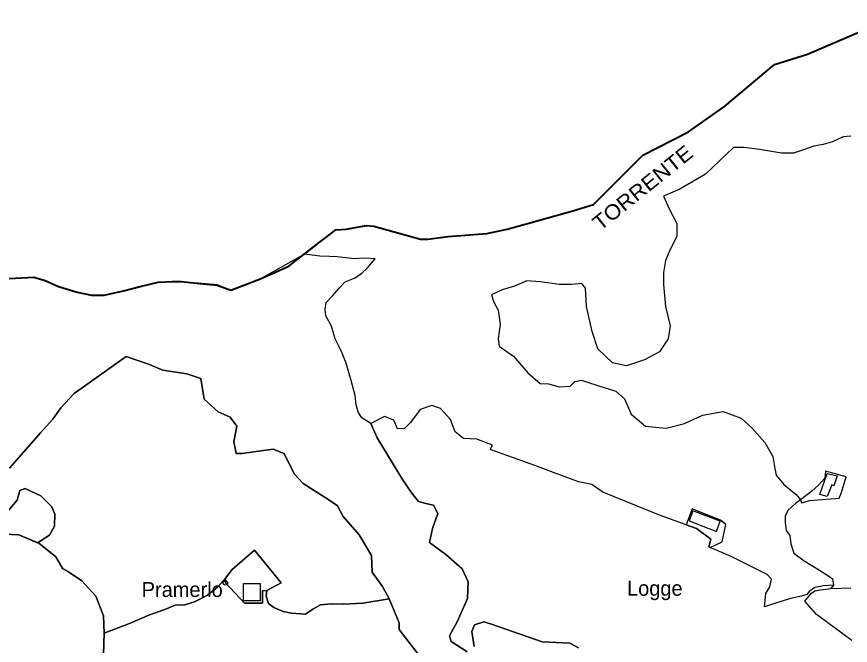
# Model space of a CAD drawing. Extents: x 645880 to 658994, y 884400 to 894744.
# Drawn here: x 652953 to 653901, y 892365 to 893080 of the extents above; entities that cross this region are included whole.
import ezdxf
from ezdxf.enums import TextEntityAlignment as Align

# ---------------------------------------------------------------- set-up
doc = ezdxf.new("R2010")
doc.units = 0
doc.header["$LTSCALE"] = 10
doc.header["$PDMODE"] = 32
doc.header["$PDSIZE"] = 5
for name, color, linetype, lineweight in [('16', 7, 'Continuous', 25), ('18', 7, 'Continuous', 25), ('2', 7, 'Continuous', 25), ('3', 7, 'Continuous', 25), ('4', 7, 'Continuous', 25), ('55', 7, 'Continuous', 25), ('59', 7, 'Continuous', 40)]:
    doc.layers.add(name, color=color, linetype=linetype, lineweight=lineweight)
doc.layers.add('60', color=7, linetype='Continuous')

msp = doc.modelspace()

# ---------------------------------------------------------------- linework, layer by layer
at = {"layer": '16'}
for p, q in [((653190.29, 892436.39), (653190.29, 892441.93)), ((653882.19, 892433.95), (653879.56, 892429.9)), ((653051.59, 892398.95), (653052.56, 892379.04))]:
    msp.add_line(p, q, dxfattribs=at)
for points in [[(653901.94, 892944.55), (653893.18, 892943.55), (653880.8, 892938.05), (653870.49, 892935.05), (653859.66, 892933.05), (653847.8, 892929.05), (653836.46, 892925.04), (653823.06, 892925.04)], [(653823.06, 892925.04), (653795.73, 892929.55), (653780.32, 892931.47), (653768.46, 892931.47), (653736.49, 892901.21)], [(653736.49, 892901.21), (653707.44, 892884.17), (653688.64, 892876.42), (653695.12, 892861.75), (653703.76, 892844.99), (653703.76, 892830.32), (653696.2, 892815.66), (653690.8, 892803.09), (653688.64, 892789.47), (653688.64, 892775.85), (653690.8, 892750.71), (653696.2, 892728.71), (653694.04, 892714.04), (653684.32, 892699.38), (653667.04, 892689.95), (653646.67, 892683.41), (653630.59, 892686.58), (653614.13, 892702.52), (653607.65, 892722.42), (653601.17, 892750.71), (653600.09, 892771.66), (653595.77, 892776.9), (653583.89, 892775.85), (653569.85, 892775.85), (653548.25, 892778.99), (653533.14, 892780.04), (653519.1, 892773.76), (653505.06, 892769.57), (653493.17, 892764.11), (653495.85, 892755.82), (653500.74, 892746.52), (653502.9, 892730.8), (653500.74, 892714.04), (653501.82, 892705.66), (653518.26, 892694.38), (653534.22, 892675.28), (653548.24, 892663.17), (653557.97, 892662.71), (653569.92, 892659.27), (653582.59, 892660.25)], [(653203.52, 892614.56), (653195.7, 892625.02), (653182.11, 892631), (653166.08, 892645.41), (653162.34, 892668.8), (653146.57, 892674.06), (653119.08, 892678.31), (653103.06, 892685.11), (653077.52, 892693.81), (653018.29, 892651.67), (653003.07, 892635.36), (652994.14, 892622.77), (652979.98, 892607.09), (652969.17, 892594.47), (652944.85, 892566.84)], [(653582.59, 892660.25), (653587.71, 892665.61), (653595.26, 892667.08), (653602.25, 892664.81), (653615.21, 892660.62), (653634.64, 892654.33), (653644.47, 892645.62), (653651.92, 892628.14), (653668.12, 892614.52), (653691.88, 892612.43), (653712.4, 892617.67), (653732.91, 892627.09), (653756.67, 892631.28), (653777, 892623.93), (653789.42, 892612.41), (653803.89, 892595.98), (653813.07, 892580.26), (653815.23, 892566.64), (653816.85, 892558.79), (653825.49, 892548.31), (653839.53, 892536.79)], [(653860.67, 892427.28), (653867.15, 892428.33), (653879.56, 892429.9), (653882.19, 892433.95), (653870.58, 892433), (653860.87, 892431.29), (653854.21, 892426.72), (653851.73, 892423.1), (653845.64, 892421.38), (653834.79, 892419.1), (653815.95, 892413.19), (653803.63, 892409.25), (653804.98, 892424.44), (653809.84, 892432.03), (653811.45, 892440.67), (653806.81, 892445.76), (653794.45, 892451.94), (653765.83, 892466.6), (653741.96, 892476.66), (653741.93, 892476.63), (653740.33, 892477.49), (653742.58, 892486.28), (653726.15, 892498.12), (653714.32, 892502.38), (653714.33, 892502.42), (653684.13, 892513.29), (653619.72, 892539.61), (653607.24, 892548.16), (653592.12, 892551.45), (653542.18, 892569.87), (653491.58, 892588.3), (653494.08, 892592.98), (653476.38, 892599.83), (653461.15, 892600.6), (653451.82, 892608.21), (653446.38, 892622.39), (653435.21, 892634.89), (653425.35, 892638.18), (653412.04, 892633.55), (653400.82, 892618.89)], [(653400.82, 892618.89), (653394.16, 892611.84), (653385.98, 892611.46), (653381.98, 892621.36), (653371.32, 892625.74), (653355.69, 892617.78), (653362.92, 892601.33), (653391.75, 892554.1), (653402.26, 892538.31), (653410.15, 892529.1), (653418.48, 892526.67), (653426.95, 892524.88), (653432.08, 892515.29), (653425.92, 892498.17), (653422.64, 892482.38), (653441.04, 892468.56), (653459.51, 892452.39), (653466.42, 892437.45), (653465.75, 892418.71), (653454.18, 892392.24), (653445.24, 892376.33), (653447.25, 892369.86), (653465.3, 892357.81)], [(653237.32, 892427.62), (653236.83, 892421.18), (653239.55, 892413), (653245.55, 892408.36), (653255.9, 892403.72), (653265.72, 892401.81), (653281.52, 892401), (653289.7, 892406.45), (653298.42, 892411.63), (653310.68, 892412.45), (653325.13, 892412.18), (653346.66, 892413.27), (653376.76, 892418.1), (653369, 892432.32), (653357.41, 892448.61), (653356.74, 892467.57), (653342.63, 892490.91), (653324.27, 892511.86), (653317.94, 892523.99), (653308.07, 892530.72), (653278.91, 892549.58), (653268.67, 892560.34), (653257.03, 892583.64), (653244.71, 892588.57), (653209.13, 892583.64), (653202.65, 892583.64), (653200.08, 892596.72), (653203.52, 892614.56)], [(652941.13, 892515.74), (652953.4, 892530.65), (652956.35, 892541.57), (652962.59, 892543.74), (652980.25, 892535.58), (652993.02, 892522.81)], [(653839.53, 892536.79), (653844.39, 892531.03), (653838.99, 892526.84), (653830.35, 892518.98), (653827.11, 892512.69), (653827.11, 892504.84), (653828.19, 892495.93), (653832.51, 892490.17), (653833.59, 892480.74), (653836.83, 892470.27), (653848.71, 892461.36), (653865.99, 892450.89), (653876.79, 892444.08), (653881.11, 892440.93), (653882.19, 892433.95), (653879.56, 892429.9), (653901.7, 892430.95)], [(652993.02, 892522.81), (652996.28, 892514.38), (652996.11, 892501.04), (652990.2, 892490.51), (652976.8, 892482.12)], [(652976.8, 892482.12), (652978.22, 892481.53), (652997.67, 892466.1), (653005.6, 892452.45), (653005.72, 892452.31), (653011.76, 892448.91), (653027.23, 892438.87), (653042.85, 892421.21), (653051.59, 892398.95)], [(653052.56, 892379.04), (653081.38, 892390.35), (653103.24, 892399.51), (653121.56, 892406.02), (653133.08, 892411.04), (653144.31, 892411.63), (653155.24, 892414.88), (653170.02, 892422.28), (653181.84, 892432.03), (653190.29, 892441.93), (653198.12, 892451.62), (653223.49, 892473.77), (653253.92, 892436.39), (653237.32, 892427.62)], [(653190.29, 892441.93), (653181.84, 892432.03), (653170.02, 892422.28), (653155.24, 892414.88), (653144.31, 892411.63)], [(653376.76, 892418.1), (653346.66, 892413.27), (653325.13, 892412.18), (653310.68, 892412.45), (653298.42, 892411.63), (653289.7, 892406.45), (653281.52, 892401), (653265.72, 892401.81), (653255.9, 892403.72), (653245.55, 892408.36), (653239.55, 892413), (653236.83, 892421.18), (653237.32, 892427.62), (653232.62, 892427.4), (653232.71, 892413.31), (653211.96, 892413.31), (653190.29, 892436.39)], [(653902.88, 892370.97), (653862.92, 892400.3), (653849.64, 892415.48), (653856.89, 892424.66), (653860.67, 892427.28)], [(653414.88, 892348.35), (653387.94, 892383.22), (653387.94, 892391.12), (653376.76, 892418.1)], [(653144.31, 892411.63), (653133.08, 892411.04), (653121.56, 892406.02), (653103.24, 892399.51)], [(653103.24, 892399.51), (653081.38, 892390.35), (653052.56, 892379.04)], [(653473.24, 892363.94), (653470.61, 892381.05), (653473.78, 892388.82), (653484.41, 892392.24), (653492.95, 892389.6), (653550.78, 892369.21), (653582.27, 892367.91), (653592.12, 892362.65)], [(653052.56, 892379.04), (653052.03, 892367.52), (653051.51, 892341.5), (653053.91, 892333.42), (653058.55, 892320.5), (653061.07, 892316.84), (653070.81, 892305.95), (653093, 892285.93), (653111.55, 892271.51), (653120.29, 892265.68), (653125.07, 892263.52), (653128.58, 892262.48), (653136.89, 892259.79), (653138.07, 892259.44), (653150.65, 892258.57), (653173.25, 892258.73), (653193.46, 892272.72), (653209.64, 892279.81), (653231.4, 892284.64), (653255.59, 892279.26)]]:
    msp.add_lwpolyline(points, dxfattribs=at)
msp.add_point((653190.29, 892436.39), dxfattribs=at)
at = {"layer": '18'}
for points in [[(653665.35, 892922.98), (653717.24, 892949.39), (653737.66, 892963.83), (653758.08, 892978.27), (653786.58, 893002.21), (653815.08, 893026.14), (653833.79, 893031.92), (653852.51, 893037.7), (653873.78, 893046.77), (653895.05, 893055.85), (653923.38, 893068.13)], [(653901.94, 892944.55), (653893.18, 892943.55), (653880.8, 892938.05), (653870.49, 892935.05), (653859.66, 892933.05), (653847.8, 892929.05), (653836.46, 892925.04), (653823.06, 892925.04), (653795.73, 892929.55), (653780.32, 892931.47), (653768.46, 892931.47), (653736.49, 892901.21)], [(653538.06, 892846.19), (653585.7, 892859.4), (653609.2, 892866.86), (653637.27, 892894.92), (653665.35, 892922.98)], [(653736.49, 892901.21), (653707.44, 892884.17), (653688.64, 892876.42), (653695.12, 892861.75), (653703.76, 892844.99), (653703.76, 892830.32), (653696.2, 892815.66), (653690.8, 892803.09), (653688.64, 892789.47), (653688.64, 892775.85), (653690.8, 892750.71), (653696.2, 892728.71), (653694.04, 892714.04), (653684.32, 892699.38), (653667.04, 892689.95), (653646.67, 892683.41), (653630.59, 892686.58), (653614.13, 892702.52), (653607.65, 892722.42), (653601.17, 892750.71), (653600.09, 892771.66), (653595.77, 892776.9), (653583.89, 892775.85), (653569.85, 892775.85), (653548.25, 892778.99), (653533.14, 892780.04), (653519.1, 892773.76), (653505.06, 892769.57), (653493.17, 892764.11), (653495.85, 892755.82), (653500.74, 892746.52), (653502.9, 892730.8), (653500.74, 892714.04), (653501.82, 892705.66), (653518.26, 892694.38), (653534.22, 892675.28), (653548.24, 892663.17), (653557.97, 892662.71), (653569.92, 892659.27), (653582.59, 892660.25)], [(653327.92, 892838.76), (653339.41, 892840.83), (653350.89, 892842.89), (653359.4, 892842.07), (653412.14, 892827.21), (653420.65, 892827.21), (653432.13, 892828.86), (653443.62, 892830.51), (653465.74, 892832.16), (653487.86, 892833.81), (653510.83, 892838.76), (653524.45, 892842.47), (653538.06, 892846.19)], [(653355.69, 892617.78), (653345.71, 892623.97), (653341.26, 892630.4), (653339.28, 892638.82), (653337.8, 892649.7), (653333.35, 892666.53), (653327.91, 892686.33), (653322.47, 892699.69), (653315.05, 892714.05), (653311.09, 892728.4), (653304.66, 892740.28), (653303.67, 892747.71), (653305.15, 892755.13), (653312.08, 892763.05), (653319.99, 892771.96), (653326.42, 892778.89), (653337.8, 892783.34), (653345.71, 892788.79), (653352.14, 892794.73), (653360.86, 892804.96), (653348.19, 892805.62), (653337.31, 892805.12), (653317.52, 892807.1), (653308.62, 892807.6), (653297.74, 892808.09), (653280.52, 892810.27), (653302.39, 892827.63), (653316.01, 892837.94), (653327.92, 892838.76)], [(653355.69, 892617.78), (653345.71, 892623.97), (653341.26, 892630.4), (653339.28, 892638.82), (653337.8, 892649.7), (653333.35, 892666.53), (653327.91, 892686.33), (653322.47, 892699.69), (653315.05, 892714.05), (653311.09, 892728.4), (653304.66, 892740.28), (653303.67, 892747.71), (653305.15, 892755.13), (653312.08, 892763.05), (653319.99, 892771.96), (653326.42, 892778.89), (653337.8, 892783.34), (653345.71, 892788.79), (653352.14, 892794.73), (653360.86, 892804.96), (653348.19, 892805.62), (653337.31, 892805.12), (653317.52, 892807.1), (653308.62, 892807.6), (653297.74, 892808.09), (653280.52, 892810.27), (653230.93, 892782.64), (653196.39, 892769.43), (653181.06, 892775.21), (653150.83, 892778.1), (653140.19, 892779.34), (653129.97, 892779.34), (653113.79, 892778.51), (653093.35, 892773.56), (653074.61, 892768.6), (653052.47, 892763.64), (653037.99, 892763.64), (653021.81, 892766.95), (653011.17, 892770.25), (653000.52, 892773.56)], [(653000.52, 892773.56), (652985.19, 892780.17), (652972.42, 892784.3), (652944.32, 892782.64)], [(652944.85, 892566.84), (652969.17, 892594.47), (652979.98, 892607.09), (652994.14, 892622.77), (653003.07, 892635.36), (653018.29, 892651.67), (653077.52, 892693.81), (653103.06, 892685.11), (653119.08, 892678.31), (653146.57, 892674.06), (653162.34, 892668.8), (653166.08, 892645.41), (653182.11, 892631)], [(653582.59, 892660.25), (653587.71, 892665.61), (653595.26, 892667.08), (653602.25, 892664.81), (653615.21, 892660.62), (653634.64, 892654.33), (653644.47, 892645.62), (653651.92, 892628.14), (653668.12, 892614.52), (653691.88, 892612.43), (653712.4, 892617.67), (653732.91, 892627.09), (653756.67, 892631.28), (653777, 892623.93), (653789.42, 892612.41), (653803.89, 892595.98), (653813.07, 892580.26), (653815.23, 892566.64), (653816.85, 892558.79), (653825.49, 892548.31), (653839.53, 892536.79), (653844.39, 892531.03), (653838.99, 892526.84), (653830.35, 892518.98), (653827.11, 892512.69), (653827.11, 892504.84), (653828.19, 892495.93), (653832.51, 892490.17), (653833.59, 892480.74), (653836.83, 892470.27), (653848.71, 892461.36), (653865.99, 892450.89), (653876.79, 892444.08), (653881.11, 892440.93), (653882.19, 892433.95), (653870.58, 892433), (653860.87, 892431.29), (653854.21, 892426.72), (653851.73, 892423.1), (653845.64, 892421.38)], [(653845.64, 892421.38), (653834.79, 892419.1), (653815.95, 892413.19), (653803.63, 892409.25), (653804.98, 892424.44), (653809.84, 892432.03), (653811.45, 892440.67), (653806.81, 892445.76), (653794.45, 892451.94), (653765.83, 892466.6), (653741.96, 892476.66), (653755.33, 892483.12), (653759.48, 892502.96), (653753.49, 892507.57), (653721.21, 892520.49), (653714.33, 892502.42), (653684.13, 892513.29), (653619.72, 892539.61), (653607.24, 892548.16), (653592.12, 892551.45), (653542.18, 892569.87), (653491.58, 892588.3), (653494.08, 892592.98), (653476.38, 892599.83), (653461.15, 892600.6), (653451.82, 892608.21), (653446.38, 892622.39), (653435.21, 892634.89), (653425.35, 892638.18), (653412.04, 892633.55), (653400.82, 892618.89), (653394.16, 892611.84), (653385.98, 892611.46), (653381.98, 892621.36), (653371.32, 892625.74), (653355.69, 892617.78)], [(653182.11, 892631), (653195.7, 892625.02), (653203.52, 892614.56), (653200.08, 892596.72), (653202.65, 892583.64), (653209.13, 892583.64), (653244.71, 892588.57), (653257.03, 892583.64), (653268.67, 892560.34), (653278.91, 892549.58), (653308.07, 892530.72), (653317.94, 892523.99), (653324.27, 892511.86), (653342.63, 892490.91), (653356.74, 892467.57), (653357.41, 892448.61), (653369, 892432.32), (653376.76, 892418.1), (653387.94, 892391.12), (653387.94, 892383.22), (653414.88, 892348.35)], [(653465.3, 892357.81), (653447.25, 892369.86), (653445.24, 892376.33), (653454.18, 892392.24), (653465.75, 892418.71), (653466.42, 892437.45), (653459.51, 892452.39), (653441.04, 892468.56), (653422.64, 892482.38), (653425.92, 892498.17), (653432.08, 892515.29), (653426.95, 892524.88), (653418.48, 892526.67), (653410.15, 892529.1), (653402.26, 892538.31), (653391.75, 892554.1), (653362.92, 892601.33), (653355.69, 892617.78)], [(652996.11, 892501.04), (652996.28, 892514.38), (652993.02, 892522.81), (652980.25, 892535.58), (652962.59, 892543.74), (652956.35, 892541.57), (652953.4, 892530.65), (652941.13, 892515.74)], [(652827.89, 892453.5), (652831.54, 892463.14), (652859.71, 892483.55), (652885.54, 892487.96), (652902.63, 892487.4), (652912.11, 892487.8), (652930.58, 892492.23), (652955.56, 892490.98), (652976.8, 892482.12), (652990.2, 892490.51), (652996.11, 892501.04)], [(653902.88, 892370.97), (653862.92, 892400.3), (653849.64, 892415.48), (653856.89, 892424.66), (653860.67, 892427.28), (653867.15, 892428.33), (653879.56, 892429.9), (653901.7, 892430.95)], [(653592.12, 892362.65), (653582.27, 892367.91), (653550.78, 892369.21), (653492.95, 892389.6), (653484.41, 892392.24), (653473.78, 892388.82), (653470.61, 892381.05), (653473.24, 892363.94)]]:
    msp.add_lwpolyline(points, dxfattribs=at)
at = {"layer": '2'}
for points in [[(653886.32, 892558.03), (653882.54, 892546.7), (653880.1, 892547.81), (653874.77, 892534.71), (653866.56, 892536.93), (653875, 892560.92)], [(653722.05, 892518.33), (653717.83, 892506.9), (653748.93, 892494.77), (653753.14, 892506.73)]]:
    msp.add_lwpolyline(points, close=True, dxfattribs=at)
at = {"layer": '3'}
for points in [[(653223.49, 892473.77), (653198.12, 892451.62), (653190.29, 892441.93), (653190.29, 892436.39)], [(653190.29, 892436.39), (653211.96, 892413.31), (653232.71, 892413.31), (653232.62, 892427.4), (653237.32, 892427.62), (653253.92, 892436.39), (653223.49, 892473.77)]]:
    msp.add_lwpolyline(points, dxfattribs=at)
msp.add_lwpolyline([(653210.93, 892435.63), (653229.97, 892435.72), (653229.97, 892416.06), (653211.02, 892415.97)], close=True, dxfattribs=at)
msp.add_point((653190.29, 892436.39), dxfattribs=at)
at = {"layer": '4'}
for points in [[(653844.39, 892531.03), (653845.79, 892527.54), (653855.25, 892530.16), (653863.78, 892531.01), (653888.68, 892532.85), (653890.99, 892539.31), (653896.62, 892556.95), (653873.05, 892563.57), (653872.08, 892555.46), (653865.17, 892547.62), (653857.33, 892540.7)], [(653753.46, 892507.54), (653721.18, 892520.46), (653714.3, 892502.39), (653726.15, 892498.12), (653742.58, 892486.28), (653740.33, 892477.49), (653741.93, 892476.63), (653755.3, 892483.09), (653759.45, 892502.93)]]:
    msp.add_lwpolyline(points, close=True, dxfattribs=at)
at = {"layer": '55'}
msp.add_lwpolyline([(653051.51, 892341.5), (653052.03, 892367.52), (653052.56, 892379.04), (653051.59, 892398.95), (653042.85, 892421.21), (653027.23, 892438.87), (653011.76, 892448.91), (653005.72, 892452.31), (653005.6, 892452.45), (652997.67, 892466.1), (652978.22, 892481.53), (652955.56, 892490.98), (652930.58, 892492.23)], dxfattribs=at)
at = {"layer": '59'}
for points in [[(653196.36, 892769.4), (653230.9, 892782.61), (653262.38, 892796.64), (653288.75, 892817.28), (653315.98, 892837.91), (653327.89, 892838.73), (653350.86, 892842.86), (653359.37, 892842.04), (653412.11, 892827.18), (653420.62, 892827.18), (653443.59, 892830.48), (653487.83, 892833.78), (653510.8, 892838.73), (653538.03, 892846.16), (653585.67, 892859.37), (653609.17, 892866.83), (653665.32, 892922.95), (653717.21, 892949.36), (653758.05, 892978.24), (653815.05, 893026.11), (653852.48, 893037.67), (653895.02, 893055.82), (653951.68, 893080.38)], [(652944.29, 892782.61), (652972.39, 892784.27), (652985.16, 892780.14), (653000.49, 892773.53), (653021.78, 892766.92), (653037.96, 892763.61), (653052.44, 892763.61), (653074.58, 892768.57), (653093.32, 892773.53), (653113.76, 892778.48), (653129.94, 892779.31), (653140.16, 892779.31), (653161.45, 892776.83), (653181.03, 892775.18), (653196.36, 892769.4)]]:
    msp.add_lwpolyline(points, dxfattribs=at)

# ---------------------------------------------------------------- texts
at = {"layer": '60', "width": 1.1}
msp.add_text('TORRENTE', height=17, rotation=38.81, dxfattribs=at).set_placement((653670.28, 892879.2), align=Align.CENTER)
at = {"layer": '60'}
for s, p in [('Pramerlo', (653141.22, 892420.37)), ('Logge', (653678.83, 892421.76))]:
    msp.add_text(s, height=17, dxfattribs=at).set_placement(p, align=Align.CENTER)

doc.saveas('drawing.dxf')
